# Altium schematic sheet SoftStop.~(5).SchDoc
size A
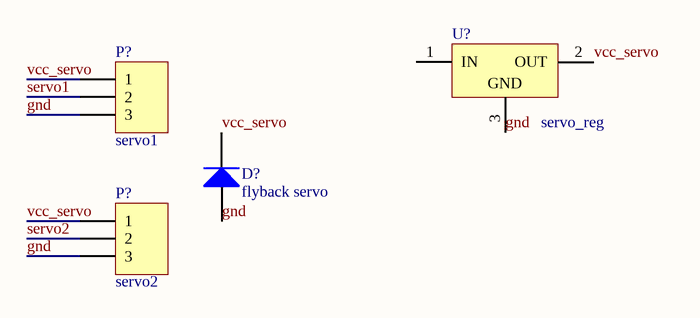
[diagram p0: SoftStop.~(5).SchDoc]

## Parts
(Parts that share a designator on the sheet are numbered #1, #2 ... from top to bottom, then left to right.)
D?  flyback servo  [DO-41]
P?#1  servo1  [HDR1X3H]
P?#2  servo2  [HDR1X3H]
U?  servo_reg  [TO220ABN]

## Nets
gnd: D?.1(A) P?#1.3 P?#2.3 U?.3(GND)
servo1: P?#1.2
servo2: P?#2.2
vcc_servo: D?.2(K) P?#1.1 P?#2.1 U?.2(OUT)

Not connected (* = marked no-connect by the designer): U? 1(IN)

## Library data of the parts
D? = Diode 1N4001: 1 Amp General Purpose Rectifier
P?#1 P?#2 = Header 3H: Header, 3-Pin, Right Angle
U? = L7805CV: Positive Voltage Regulator; Note: Tab is connected to pin 3 (GND).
